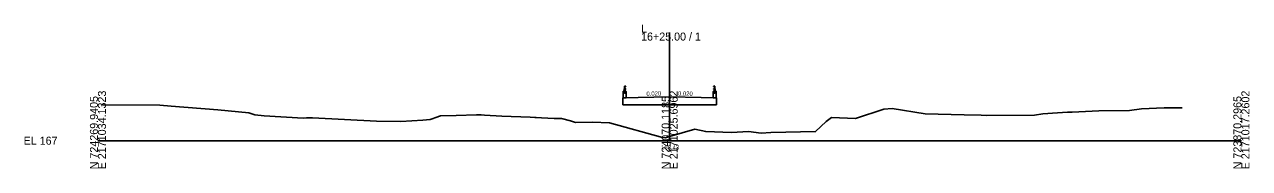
# Model space of a CAD drawing. Extents: x -26 to 2803, y -10 to 9553.
# Drawn here: x -25.7 to 402.8, y 8490.3 to 8540.6 of the extents above; entities that cross this region are included whole.
import ezdxf

# ---------------------------------------------------------------- set-up
doc = ezdxf.new("R2010")
doc.units = 0
for name, color, linetype in [('Exist Cross Section Cell', 7, 'Continuous'), ('Exist XS Center Line Elevation Label', 7, 'Continuous'), ('Exist XS Ground Line', 7, 'Continuous'), ('Prop XS Bridge', 7, 'Continuous'), ('Prop XS Dump Level', 7, 'Continuous'), ('Prop XS SE Text', 7, 'Continuous')]:
    doc.layers.add(name, color=color, linetype=linetype)

msp = doc.modelspace()

# ---------------------------------------------------------------- linework, layer by layer
at = {"layer": 'Exist Cross Section Cell'}
for p, q in [((200, 8500), (200, 8537.76)), ((0, 8500), (200, 8500)), ((200, 8500), (400, 8500))]:
    msp.add_line(p, q, dxfattribs=at)
at = {"layer": 'Exist XS Ground Line'}
msp.add_lwpolyline([(1.36, 8512.59), (1.81, 8512.52), (21.62, 8512.37), (25.64, 8512.09), (41.89, 8510.73), (52.74, 8509.68), (54.94, 8509.03), (58.13, 8508.64), (71.82, 8507.92), (72.92, 8507.95), (73.26, 8507.95), (73.64, 8507.96), (74.26, 8507.96), (75.01, 8507.93), (97.48, 8506.78), (105.91, 8506.74), (113.71, 8507.19), (116.21, 8507.38), (116.9, 8507.66), (118.16, 8508.05), (119.85, 8508.74), (125.3, 8508.8), (132.47, 8509.04), (134.1, 8509.04), (135.19, 8508.93), (141.26, 8508.56), (151.25, 8508.16), (152.89, 8508.11), (153.32, 8508.1), (155.12, 8507.97), (159.58, 8507.73), (162.12, 8507.75), (165.26, 8506.89), (167.05, 8506.41), (173.01, 8506.45), (179.01, 8506.27), (197.45, 8501.06), (198.51, 8501), (200, 8501.43), (208.83, 8503.98), (212.63, 8503.17), (221.6, 8502.85), (227.59, 8503.27), (232.05, 8502.65), (235.43, 8502.92), (251.07, 8503.18), (254.8, 8506.71), (256.64, 8508.1), (265, 8507.8), (274.97, 8511.02), (277.89, 8511.29), (289.33, 8509.41), (302.97, 8509.06), (309.02, 8508.9), (310.73, 8508.82), (327.62, 8508.95), (330.57, 8509.34), (335.7, 8509.76), (339.22, 8509.98), (340.79, 8510.02), (350.08, 8510.43), (360.89, 8510.56), (365.11, 8511.12), (372.94, 8511.48), (378.9, 8511.51), (379.32, 8511.51)], dxfattribs=at)
at = {"layer": 'Prop XS Bridge'}
for p, q in [((183.57, 8514.95), (183.62, 8515.01)), ((183.57, 8514.95), (183.57, 8512.5)), ((183.7, 8515.01), (183.62, 8515.01)), ((183.69, 8517.23), (183.73, 8517.28)), ((183.69, 8517.23), (183.69, 8515.01)), ((184.75, 8515.01), (183.7, 8515.01)), ((184.7, 8517.28), (183.73, 8517.28)), ((184.19, 8519.07), (184.07, 8517.35)), ((184.07, 8517.37), (184.07, 8517.4)), ((184.07, 8517.32), (184.07, 8517.35)), ((184.2, 8517.24), (184.11, 8517.24)), ((184.2, 8517.23), (184.11, 8517.23)), ((184.15, 8517.2), (184.11, 8517.2)), ((184.15, 8517.19), (184.11, 8517.19)), ((184.15, 8517.16), (184.11, 8517.16)), ((184.15, 8517.15), (184.11, 8517.15)), ((184.15, 8517.12), (184.11, 8517.12)), ((184.15, 8517.11), (184.11, 8517.11)), ((184.15, 8517.08), (184.11, 8517.08)), ((184.15, 8517.07), (184.11, 8517.07)), ((184.15, 8517.22), (184.13, 8517.22)), ((184.15, 8517.21), (184.13, 8517.21)), ((184.15, 8517.18), (184.13, 8517.18)), ((184.15, 8517.17), (184.13, 8517.17)), ((184.15, 8517.14), (184.13, 8517.14)), ((184.15, 8517.13), (184.13, 8517.13)), ((184.15, 8517.1), (184.13, 8517.1)), ((184.15, 8517.09), (184.13, 8517.09)), ((184.18, 8517.39), (184.14, 8517.39)), ((184.14, 8517.39), (184.14, 8517.35)), ((184.14, 8517.24), (184.14, 8517.32)), ((184.16, 8517.22), (184.15, 8517.22)), ((184.15, 8517.22), (184.15, 8516.72)), ((184.18, 8517.22), (184.16, 8517.22)), ((184.16, 8517.22), (184.16, 8516.72)), ((184.18, 8517.21), (184.16, 8517.21)), ((184.2, 8517.2), (184.16, 8517.2)), ((184.2, 8517.19), (184.16, 8517.19)), ((184.18, 8517.18), (184.16, 8517.18)), ((184.18, 8517.17), (184.16, 8517.17)), ((184.2, 8517.16), (184.16, 8517.16)), ((184.2, 8517.15), (184.16, 8517.15)), ((184.18, 8517.14), (184.16, 8517.14)), ((184.18, 8517.13), (184.16, 8517.13)), ((184.2, 8517.12), (184.16, 8517.12)), ((184.2, 8517.11), (184.16, 8517.11)), ((184.18, 8517.1), (184.16, 8517.1)), ((184.18, 8517.09), (184.16, 8517.09)), ((184.2, 8517.08), (184.16, 8517.08)), ((184.2, 8517.07), (184.16, 8517.07)), ((184.18, 8517.35), (184.18, 8517.39)), ((184.18, 8517.24), (184.18, 8517.32)), ((184.19, 8519.07), (184.3, 8519.1)), ((184.19, 8517.32), (184.19, 8519.07)), ((184.19, 8518.25), (184.19, 8518.25)), ((184.43, 8516.67), (184.21, 8516.67)), ((184.43, 8516.65), (184.21, 8516.65)), ((184.37, 8519.1), (184.3, 8519.1)), ((184.3, 8517.32), (184.3, 8519.1)), ((184.37, 8517.32), (184.37, 8519.1)), ((184.43, 8519.07), (184.43, 8518.98)), ((184.43, 8518.88), (184.43, 8518.98)), ((184.43, 8518.14), (184.43, 8518.04)), ((184.43, 8517.94), (184.43, 8518.04)), ((184.53, 8517.24), (184.44, 8517.24)), ((184.53, 8517.23), (184.44, 8517.23)), ((184.48, 8517.2), (184.44, 8517.2)), ((184.48, 8517.19), (184.44, 8517.19)), ((184.48, 8517.16), (184.44, 8517.16)), ((184.48, 8517.15), (184.44, 8517.15)), ((184.48, 8517.12), (184.44, 8517.12)), ((184.48, 8517.11), (184.44, 8517.11)), ((184.48, 8517.08), (184.44, 8517.08)), ((184.48, 8517.07), (184.44, 8517.07)), ((184.48, 8517.22), (184.46, 8517.22)), ((184.48, 8517.21), (184.46, 8517.21)), ((184.48, 8517.18), (184.46, 8517.18)), ((184.48, 8517.17), (184.46, 8517.17)), ((184.48, 8517.14), (184.46, 8517.14)), ((184.48, 8517.13), (184.46, 8517.13)), ((184.48, 8517.1), (184.46, 8517.1)), ((184.48, 8517.09), (184.46, 8517.09)), ((184.51, 8517.4), (184.47, 8517.4)), ((184.47, 8517.4), (184.47, 8517.36)), ((184.47, 8517.24), (184.47, 8517.32)), ((184.49, 8517.22), (184.48, 8517.22)), ((184.48, 8517.22), (184.48, 8516.72)), ((184.51, 8517.22), (184.49, 8517.22)), ((184.49, 8517.22), (184.49, 8516.72)), ((184.51, 8517.21), (184.49, 8517.21)), ((184.53, 8517.2), (184.49, 8517.2)), ((184.53, 8517.19), (184.49, 8517.19)), ((184.51, 8517.18), (184.49, 8517.18)), ((184.51, 8517.17), (184.49, 8517.17)), ((184.53, 8517.16), (184.49, 8517.16)), ((184.53, 8517.15), (184.49, 8517.15)), ((184.51, 8517.14), (184.49, 8517.14)), ((184.51, 8517.13), (184.49, 8517.13)), ((184.53, 8517.12), (184.49, 8517.12)), ((184.53, 8517.11), (184.49, 8517.11)), ((184.51, 8517.1), (184.49, 8517.1)), ((184.51, 8517.09), (184.49, 8517.09)), ((184.53, 8517.08), (184.49, 8517.08)), ((184.53, 8517.07), (184.49, 8517.07)), ((184.51, 8517.36), (184.51, 8517.4)), ((184.51, 8517.24), (184.51, 8517.32)), ((184.7, 8517.28), (184.75, 8517.23)), ((184.75, 8517.23), (184.75, 8515.01)), ((189, 8515.09), (184.75, 8515.01)), ((189, 8515.09), (200, 8515.31)), ((200, 8515.31), (211, 8515.09)), ((211, 8515.09), (215.25, 8515.01)), ((215.25, 8517.23), (215.3, 8517.28)), ((215.25, 8517.23), (215.25, 8515.01)), ((215.25, 8515.01), (216.3, 8515.01)), ((215.3, 8517.28), (216.27, 8517.28)), ((215.47, 8517.24), (215.56, 8517.24)), ((215.47, 8517.23), (215.56, 8517.23)), ((215.47, 8517.2), (215.51, 8517.2)), ((215.47, 8517.19), (215.51, 8517.19)), ((215.47, 8517.16), (215.51, 8517.16)), ((215.47, 8517.15), (215.51, 8517.15)), ((215.47, 8517.12), (215.51, 8517.12)), ((215.47, 8517.11), (215.51, 8517.11)), ((215.47, 8517.08), (215.51, 8517.08)), ((215.47, 8517.07), (215.51, 8517.07)), ((215.49, 8517.36), (215.49, 8517.4)), ((215.49, 8517.4), (215.53, 8517.4)), ((215.49, 8517.24), (215.49, 8517.32)), ((215.49, 8517.22), (215.51, 8517.22)), ((215.49, 8517.21), (215.51, 8517.21)), ((215.49, 8517.18), (215.51, 8517.18)), ((215.49, 8517.17), (215.51, 8517.17)), ((215.49, 8517.14), (215.51, 8517.14)), ((215.49, 8517.13), (215.51, 8517.13)), ((215.49, 8517.1), (215.51, 8517.1)), ((215.49, 8517.09), (215.51, 8517.09)), ((215.51, 8517.22), (215.52, 8517.22)), ((215.51, 8517.22), (215.51, 8516.72)), ((215.52, 8517.22), (215.54, 8517.22)), ((215.52, 8517.22), (215.52, 8516.72)), ((215.52, 8517.21), (215.54, 8517.21)), ((215.52, 8517.2), (215.56, 8517.2)), ((215.52, 8517.19), (215.56, 8517.19)), ((215.52, 8517.18), (215.54, 8517.18)), ((215.52, 8517.17), (215.54, 8517.17)), ((215.52, 8517.16), (215.56, 8517.16)), ((215.52, 8517.15), (215.56, 8517.15)), ((215.52, 8517.14), (215.54, 8517.14)), ((215.52, 8517.13), (215.54, 8517.13)), ((215.52, 8517.12), (215.56, 8517.12)), ((215.52, 8517.11), (215.56, 8517.11)), ((215.52, 8517.1), (215.54, 8517.1)), ((215.52, 8517.09), (215.54, 8517.09)), ((215.52, 8517.08), (215.56, 8517.08)), ((215.52, 8517.07), (215.56, 8517.07)), ((215.53, 8517.4), (215.53, 8517.36)), ((215.53, 8517.24), (215.53, 8517.32)), ((215.57, 8519.07), (215.57, 8518.98)), ((215.57, 8518.88), (215.57, 8518.98)), ((215.57, 8518.14), (215.57, 8518.04)), ((215.57, 8517.94), (215.57, 8518.04)), ((215.57, 8516.67), (215.79, 8516.67)), ((215.57, 8516.65), (215.79, 8516.65)), ((215.63, 8519.1), (215.7, 8519.1)), ((215.63, 8517.32), (215.63, 8519.1)), ((215.81, 8519.07), (215.7, 8519.1)), ((215.7, 8517.32), (215.7, 8519.1)), ((215.8, 8517.24), (215.89, 8517.24)), ((215.8, 8517.23), (215.89, 8517.23)), ((215.8, 8517.2), (215.84, 8517.2)), ((215.8, 8517.19), (215.84, 8517.19)), ((215.8, 8517.16), (215.84, 8517.16)), ((215.8, 8517.15), (215.84, 8517.15)), ((215.8, 8517.12), (215.84, 8517.12)), ((215.8, 8517.11), (215.84, 8517.11)), ((215.8, 8517.08), (215.84, 8517.08)), ((215.8, 8517.07), (215.84, 8517.07)), ((215.81, 8517.32), (215.81, 8519.07)), ((215.81, 8519.07), (215.93, 8517.35)), ((215.81, 8518.25), (215.81, 8518.25)), ((215.82, 8517.35), (215.82, 8517.39)), ((215.82, 8517.39), (215.86, 8517.39)), ((215.82, 8517.24), (215.82, 8517.32)), ((215.82, 8517.22), (215.84, 8517.22)), ((215.82, 8517.21), (215.84, 8517.21)), ((215.82, 8517.18), (215.84, 8517.18)), ((215.82, 8517.17), (215.84, 8517.17)), ((215.82, 8517.14), (215.84, 8517.14)), ((215.82, 8517.13), (215.84, 8517.13)), ((215.82, 8517.1), (215.84, 8517.1)), ((215.82, 8517.09), (215.84, 8517.09)), ((215.84, 8517.22), (215.85, 8517.22)), ((215.84, 8517.22), (215.84, 8516.72)), ((215.85, 8517.22), (215.87, 8517.22)), ((215.85, 8517.22), (215.85, 8516.72)), ((215.85, 8517.21), (215.87, 8517.21)), ((215.85, 8517.2), (215.89, 8517.2)), ((215.85, 8517.19), (215.89, 8517.19)), ((215.85, 8517.18), (215.87, 8517.18)), ((215.85, 8517.17), (215.87, 8517.17)), ((215.85, 8517.16), (215.89, 8517.16)), ((215.85, 8517.15), (215.89, 8517.15)), ((215.85, 8517.14), (215.87, 8517.14)), ((215.85, 8517.13), (215.87, 8517.13)), ((215.85, 8517.12), (215.89, 8517.12)), ((215.85, 8517.11), (215.89, 8517.11)), ((215.85, 8517.1), (215.87, 8517.1)), ((215.85, 8517.09), (215.87, 8517.09)), ((215.85, 8517.08), (215.89, 8517.08)), ((215.85, 8517.07), (215.89, 8517.07)), ((215.86, 8517.39), (215.86, 8517.35)), ((215.86, 8517.24), (215.86, 8517.32)), ((215.93, 8517.37), (215.93, 8517.4)), ((215.93, 8517.32), (215.93, 8517.35)), ((216.27, 8517.28), (216.31, 8517.23)), ((216.3, 8515.01), (216.38, 8515.01)), ((216.31, 8517.23), (216.31, 8515.01)), ((216.43, 8514.95), (216.38, 8515.01)), ((216.43, 8514.95), (216.43, 8512.5)), ((216.43, 8512.5), (183.57, 8512.5))]:
    msp.add_line(p, q, dxfattribs=at)
for points in [[(184.55, 8517.28), (184.55, 8517.32), (184.39, 8517.32), (184.39, 8517.69), (184.37, 8517.69), (184.37, 8517.32), (184.07, 8517.32), (184.07, 8517.34), (184.07, 8517.34), (184.07, 8517.28), (184.21, 8517.28), (184.21, 8517.3), (184.35, 8517.3), (184.35, 8517.28), (184.55, 8517.28)], [(184.11, 8517.24), (184.11, 8517.23), (184.13, 8517.22), (184.13, 8517.21), (184.11, 8517.2), (184.11, 8517.19), (184.13, 8517.18), (184.13, 8517.17), (184.11, 8517.16), (184.11, 8517.15), (184.13, 8517.14), (184.13, 8517.13), (184.11, 8517.12), (184.11, 8517.11), (184.13, 8517.1), (184.13, 8517.09), (184.11, 8517.08), (184.11, 8517.07)], [(184.2, 8517.31), (184.2, 8517.32), (184.16, 8517.32), (184.12, 8517.32), (184.12, 8517.31)], [(184.19, 8517.32), (184.19, 8517.35), (184.18, 8517.35), (184.13, 8517.35), (184.13, 8517.35), (184.13, 8517.32), (184.19, 8517.32), (184.17, 8517.32), (184.17, 8517.35), (184.17, 8517.35), (184.17, 8517.35), (184.16, 8517.35), (184.15, 8517.35), (184.15, 8517.35), (184.15, 8517.32), (184.15, 8517.35), (184.14, 8517.35)], [(184.2, 8517.24), (184.2, 8517.23), (184.18, 8517.22), (184.18, 8517.21), (184.2, 8517.2), (184.2, 8517.19), (184.18, 8517.18), (184.18, 8517.17), (184.2, 8517.16), (184.2, 8517.15), (184.18, 8517.14), (184.18, 8517.13), (184.2, 8517.12), (184.2, 8517.11), (184.18, 8517.1), (184.18, 8517.09), (184.2, 8517.08), (184.2, 8517.07)], [(184.37, 8518.85), (184.37, 8518.9), (184.39, 8518.9), (184.39, 8518.89), (184.39, 8518.89), (184.39, 8518.87), (184.42, 8518.87), (184.42, 8518.9), (184.42, 8518.98), (184.42, 8519.05), (184.42, 8519.08), (184.39, 8519.08), (184.39, 8519.06), (184.39, 8519.06), (184.39, 8519.05), (184.37, 8519.05), (184.37, 8519.1)], [(184.37, 8517.92), (184.37, 8517.96), (184.39, 8517.96), (184.39, 8517.95), (184.39, 8517.95), (184.39, 8517.93), (184.42, 8517.93), (184.42, 8517.96), (184.42, 8518.04), (184.42, 8518.11), (184.42, 8518.14), (184.39, 8518.14), (184.39, 8518.12), (184.39, 8518.12), (184.39, 8518.12), (184.37, 8518.12), (184.37, 8518.16)], [(184.44, 8517.24), (184.44, 8517.23), (184.46, 8517.22), (184.46, 8517.21), (184.44, 8517.2), (184.44, 8517.19), (184.46, 8517.18), (184.46, 8517.17), (184.44, 8517.16), (184.44, 8517.15), (184.46, 8517.14), (184.46, 8517.13), (184.44, 8517.12), (184.44, 8517.11), (184.46, 8517.1), (184.46, 8517.09), (184.44, 8517.08), (184.44, 8517.07)], [(184.53, 8517.32), (184.53, 8517.33), (184.49, 8517.33), (184.45, 8517.33), (184.45, 8517.32)], [(184.52, 8517.33), (184.52, 8517.36), (184.51, 8517.36), (184.46, 8517.36), (184.46, 8517.36), (184.46, 8517.33), (184.52, 8517.33), (184.5, 8517.33), (184.5, 8517.36), (184.5, 8517.36), (184.5, 8517.36), (184.49, 8517.36), (184.48, 8517.36), (184.48, 8517.36), (184.48, 8517.33), (184.48, 8517.36), (184.47, 8517.36)], [(184.53, 8517.24), (184.53, 8517.23), (184.51, 8517.22), (184.51, 8517.21), (184.53, 8517.2), (184.53, 8517.19), (184.51, 8517.18), (184.51, 8517.17), (184.53, 8517.16), (184.53, 8517.15), (184.51, 8517.14), (184.51, 8517.13), (184.53, 8517.12), (184.53, 8517.11), (184.51, 8517.1), (184.51, 8517.09), (184.53, 8517.08), (184.53, 8517.07)], [(215.45, 8517.28), (215.45, 8517.32), (215.61, 8517.32), (215.61, 8517.69), (215.63, 8517.69), (215.63, 8517.32), (215.93, 8517.32), (215.93, 8517.34), (215.93, 8517.34), (215.93, 8517.28), (215.79, 8517.28), (215.79, 8517.3), (215.65, 8517.3), (215.65, 8517.28), (215.45, 8517.28)], [(215.47, 8517.32), (215.47, 8517.33), (215.51, 8517.33), (215.55, 8517.33), (215.55, 8517.32)], [(215.47, 8517.24), (215.47, 8517.23), (215.49, 8517.22), (215.49, 8517.21), (215.47, 8517.2), (215.47, 8517.19), (215.49, 8517.18), (215.49, 8517.17), (215.47, 8517.16), (215.47, 8517.15), (215.49, 8517.14), (215.49, 8517.13), (215.47, 8517.12), (215.47, 8517.11), (215.49, 8517.1), (215.49, 8517.09), (215.47, 8517.08), (215.47, 8517.07)], [(215.48, 8517.33), (215.48, 8517.36), (215.49, 8517.36), (215.54, 8517.36), (215.54, 8517.36), (215.54, 8517.33), (215.48, 8517.33), (215.5, 8517.33), (215.5, 8517.36), (215.5, 8517.36), (215.5, 8517.36), (215.51, 8517.36), (215.52, 8517.36), (215.52, 8517.36), (215.52, 8517.33), (215.52, 8517.36), (215.53, 8517.36)], [(215.56, 8517.24), (215.56, 8517.23), (215.54, 8517.22), (215.54, 8517.21), (215.56, 8517.2), (215.56, 8517.19), (215.54, 8517.18), (215.54, 8517.17), (215.56, 8517.16), (215.56, 8517.15), (215.54, 8517.14), (215.54, 8517.13), (215.56, 8517.12), (215.56, 8517.11), (215.54, 8517.1), (215.54, 8517.09), (215.56, 8517.08), (215.56, 8517.07)], [(215.63, 8518.85), (215.63, 8518.9), (215.61, 8518.9), (215.61, 8518.89), (215.61, 8518.89), (215.61, 8518.87), (215.58, 8518.87), (215.58, 8518.9), (215.58, 8518.98), (215.58, 8519.05), (215.58, 8519.08), (215.61, 8519.08), (215.61, 8519.06), (215.61, 8519.06), (215.61, 8519.05), (215.63, 8519.05), (215.63, 8519.1)], [(215.63, 8517.92), (215.63, 8517.96), (215.61, 8517.96), (215.61, 8517.95), (215.61, 8517.95), (215.61, 8517.93), (215.58, 8517.93), (215.58, 8517.96), (215.58, 8518.04), (215.58, 8518.11), (215.58, 8518.14), (215.61, 8518.14), (215.61, 8518.12), (215.61, 8518.12), (215.61, 8518.12), (215.63, 8518.12), (215.63, 8518.16)], [(215.8, 8517.31), (215.8, 8517.32), (215.84, 8517.32), (215.88, 8517.32), (215.88, 8517.31)], [(215.8, 8517.24), (215.8, 8517.23), (215.82, 8517.22), (215.82, 8517.21), (215.8, 8517.2), (215.8, 8517.19), (215.82, 8517.18), (215.82, 8517.17), (215.8, 8517.16), (215.8, 8517.15), (215.82, 8517.14), (215.82, 8517.13), (215.8, 8517.12), (215.8, 8517.11), (215.82, 8517.1), (215.82, 8517.09), (215.8, 8517.08), (215.8, 8517.07)], [(215.81, 8517.32), (215.81, 8517.35), (215.82, 8517.35), (215.87, 8517.35), (215.87, 8517.35), (215.87, 8517.32), (215.81, 8517.32), (215.83, 8517.32), (215.83, 8517.35), (215.83, 8517.35), (215.83, 8517.35), (215.84, 8517.35), (215.85, 8517.35), (215.85, 8517.35), (215.85, 8517.32), (215.85, 8517.35), (215.86, 8517.35)], [(215.89, 8517.24), (215.89, 8517.23), (215.87, 8517.22), (215.87, 8517.21), (215.89, 8517.2), (215.89, 8517.19), (215.87, 8517.18), (215.87, 8517.17), (215.89, 8517.16), (215.89, 8517.15), (215.87, 8517.14), (215.87, 8517.13), (215.89, 8517.12), (215.89, 8517.11), (215.87, 8517.1), (215.87, 8517.09), (215.89, 8517.08), (215.89, 8517.07)]]:
    msp.add_lwpolyline(points, dxfattribs=at)
for centre in [(184.12, 8517.09), (184.53, 8517.09), (215.47, 8517.09), (215.88, 8517.09)]:
    msp.add_circle(centre, 0.00793, dxfattribs=at)
for centre, radius, start, end in [((184.21, 8516.72), 0.0665, 180, 270), ((184.21, 8516.72), 0.0507, 180, 270), ((184.44, 8519.07), 0.00744, 90, 180), ((184.44, 8518.88), 0.00744, 180, 270), ((184.44, 8518.14), 0.00744, 90, 180), ((184.44, 8517.94), 0.00744, 180, 270), ((184.43, 8516.72), 0.0507, 270, 0), ((184.43, 8516.72), 0.0665, 270, 0), ((215.57, 8516.72), 0.0665, 180, 270), ((215.57, 8516.72), 0.0507, 180, 270), ((215.56, 8519.07), 0.00744, 0, 90), ((215.56, 8518.88), 0.00744, 270, 360), ((215.56, 8518.14), 0.00744, 0, 90), ((215.56, 8517.94), 0.00744, 270, 360), ((215.79, 8516.72), 0.0507, 270, 0), ((215.79, 8516.72), 0.0665, 270, 0)]:
    msp.add_arc(centre, radius, start, end, dxfattribs=at)
for centre, major_axis, ratio, start_param, end_param in [((184.37, 8518.98), (0.318, 0), 0.39036, 6.282787, 7.853967), ((184.37, 8518.98), (0.318, 0), 0.39036, 4.712404, 6.282787), ((184.37, 8518.04), (0.318, 0), 0.39036, 6.282787, 7.853967), ((184.37, 8518.04), (0.318, 0), 0.39036, 4.712404, 6.282787), ((184.44, 8518.98), (0.211, 0), 0.495501, 6.282718, 7.853881), ((184.44, 8518.98), (0.211, 0), 0.495501, 4.712489, 6.282718), ((184.44, 8518.04), (0.211, 0), 0.495501, 6.282718, 7.853881), ((184.44, 8518.04), (0.211, 0), 0.495501, 4.712489, 6.282718), ((215.63, 8518.98), (-0.318, 0), 0.39036, 4.712404, 6.283584), ((215.63, 8518.98), (-0.318, 0), 0.39036, 0.000398, 1.570782), ((215.63, 8518.04), (-0.318, 0), 0.39036, 4.712404, 6.283584), ((215.63, 8518.04), (-0.318, 0), 0.39036, 0.000398, 1.570782), ((215.56, 8518.98), (-0.211, 0), 0.495501, 4.712489, 6.283652), ((215.56, 8518.98), (-0.211, 0), 0.495501, 0.000467, 1.570696), ((215.56, 8518.04), (-0.211, 0), 0.495501, 4.712489, 6.283652), ((215.56, 8518.04), (-0.211, 0), 0.495501, 0.000467, 1.570696)]:
    msp.add_ellipse(centre, major_axis=major_axis, ratio=ratio, start_param=start_param, end_param=end_param, dxfattribs=at)
at = {"layer": 'Prop XS Dump Level'}
for p, q in [((189, 8515.09), (200, 8515.31)), ((200, 8515.31), (211, 8515.09))]:
    msp.add_line(p, q, dxfattribs=at)

# ---------------------------------------------------------------- texts
at = {"layer": 'Exist Cross Section Cell'}
for s, p in [('16+25.00 / 1', (190, 8534.96)), ('L', (190, 8537.76)), ('EL 167', (-26, 8498.6))]:
    msp.add_text(s, height=2.8, dxfattribs=at).set_placement(p)
for s, p in [('N 724269.9405', (0, 8490)), ('E 2171034.1323', (2.8, 8490)), ('N 724070.1185', (200, 8490)), ('E 2171025.6962', (202.8, 8490)), ('N 723870.2965', (400, 8490)), ('E 2171017.2602', (402.8, 8490))]:
    msp.add_text(s, height=2.8, rotation=90, dxfattribs=at).set_placement(p)
at = {"layer": 'Exist XS Center Line Elevation Label'}
msp.add_text('168.43', height=1.5, dxfattribs=at).set_placement((196.99, 8496.93))
at = {"layer": 'Prop XS SE Text'}
for rotation, p in [(1.1458, (191.88, 8515.65)), (358.8542, (202.88, 8515.75))]:
    msp.add_text('0.020', height=1.5, rotation=rotation, dxfattribs=at).set_placement(p)

doc.saveas('drawing.dxf')
